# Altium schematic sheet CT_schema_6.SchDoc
size 287 x 160 mm
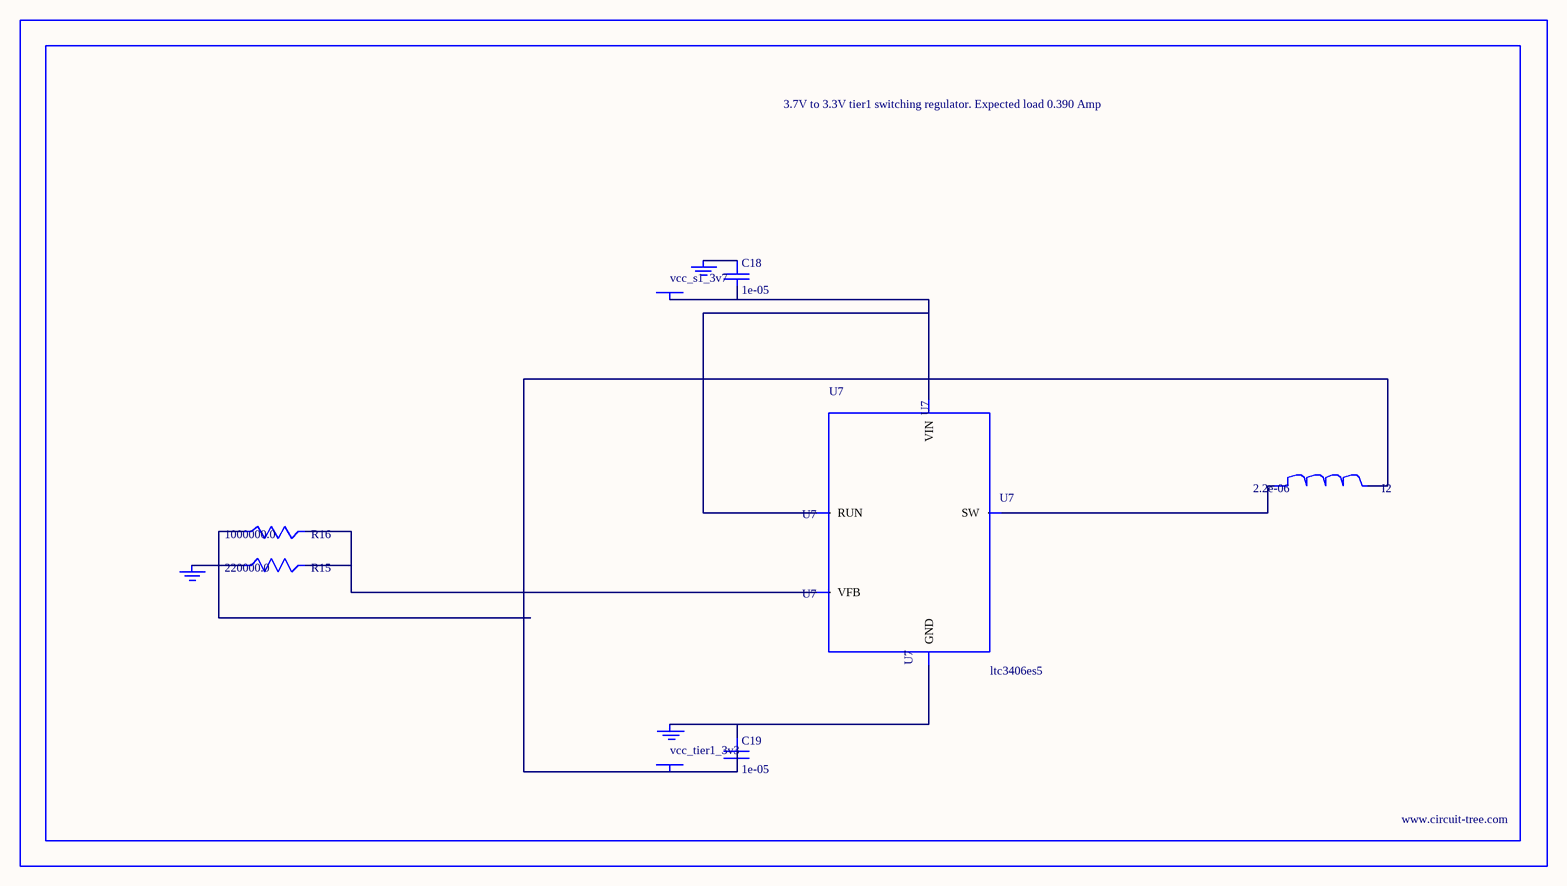
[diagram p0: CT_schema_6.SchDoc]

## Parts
BORDER5  (no value)
C18  1e-05  [C0805]
C19  1e-05  [C0805]
GND_INSTANCE_5_0  (no value)
GND_INSTANCE_5_1  (no value)
GND_INSTANCE_5_2  (no value)
I2  2.2e-06  [L0805]
POWER_INSTANCE_5_0  vcc_tier1_3v3
POWER_INSTANCE_5_1  vcc_s1_3v7
R15  220000.0  [R0603]
R16  1000000.0  [R0603]
U7  ltc3406es5  [TSOT-23-5]

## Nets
NetC18_1: C18.1 GND_INSTANCE_5_1.0(GND)
NetC18_2: C18.2 POWER_INSTANCE_5_1.0(PWR) U7.1(RUN) U7.4(VIN)
NetC19_1: C19.1 GND_INSTANCE_5_0.0(GND) U7.2(GND)
NetC19_2: C19.2 I2.2 POWER_INSTANCE_5_0.0(PWR) R16.1
NetGND_INSTANCE_5_2_0: GND_INSTANCE_5_2.0(GND) R15.1
NetI2_1: I2.1 U7.3(SW)
NetR15_2: R15.2 R16.2 U7.5(VFB)

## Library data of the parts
BORDER5 = BORDER_PAGE5
C18 C19 = C0805C106K8RACTU
GND_INSTANCE_5_0-GND_INSTANCE_5_2 = GND
I2 = L0805C2R2MDWIT
POWER_INSTANCE_5_0 POWER_INSTANCE_5_1 = PWR
R15 = RC0603JR-07220KL
R16 = RC0603JR-071ML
